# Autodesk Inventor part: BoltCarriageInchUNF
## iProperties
Author: dianat
Shininess: 25.0
PropertySet Name: _Private Model Information
Length Units: 11272
Angle Units: 11286
Time Units: 11279
Mass Units: 11290
Length Display Precision: 3
Angle Display Precision: 2
Compacted: True
Created: 2001-09
Part Number: BoltCarriageInchUNF
Description: Bolt Carriage-Round Head,1/4x0.5
Document SubType Name: Modeling
Designer: dianat
Material: Steel, Mild
Control State: 0
Master: False
Checked Out: False
PropertySet Name: Design Tracking Control
Density: 7.86
Volumn: 1.2093757249227457
Area: 9.193249513056257
PropertySet Name: Model Information
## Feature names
1. Extrusion1
2. Revolution2
3. Fillet1
4. Extrusion2
5. Revolution3
6. Fillet2
7. Chamfer1
